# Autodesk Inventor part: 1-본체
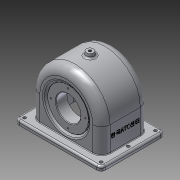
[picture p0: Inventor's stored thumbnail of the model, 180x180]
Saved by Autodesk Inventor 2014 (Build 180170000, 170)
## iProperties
Created: 2015-09
Part Number: 1-본체
Material: 알루미늄 6061
Document SubType Name: Modeling
Designer: Administrator
Density: 2.71 g/cm^3
Appearance: 알루미늄 - 평지
Mass: 735.164 g
Surface Area: 899.785 cm^2
Volume: 271.278 cm^3
Author: Administrator
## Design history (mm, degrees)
sketch "스케치2"
  geometry: L1 (57, 40)-(57, -7); L2 (-57, 40)-(-57, -7); L3 (57, -7)-(-57, -7); C1 r 51 at (0, 40); A1 r 57 centre (0, 40) between (57, 40) and (-57, 40); 2 further points
  constraints: 6 end point, 2 centre point, 2 point on circle, 2 tangent, 1 perpendicular, 1 vertical alignment
  dimensions: "d4" = 51 radius of C1; "d6" = 6 radial gap between concentric circles of C1 A1; "d27" = 40 distance of point (0, 0) C1.centre
extrude "돌출2" join sketch "스케치2" stored distance "d7" = 77; taper "d8" = 0 deg
fillet "모깎기1" dims "d11" = 14
feature "쉘4" dims "d30" = 6, "d31" = 5
sketch "스케치12"
  geometry: L1 (-43, -38.5)-(43, -38.5) reference; L2 (-57, -24.5)-(-57, 24.5) reference; L3 (43, 38.5)-(-43, 38.5) reference; L4 (57, -24.5)-(57, 24.5) reference; L5 (-70, -52)-(70, -52); L6 (70, -52)-(70, 52); L7 (70, 52)-(-70, 52); L8 (-70, 52)-(-70, -52); A1 r 14 centre (-43, -24.5) between (-57, -24.5) and (-43, -38.5) reference; A2 r 14 centre (-43, 24.5) between (-43, 38.5) and (-57, 24.5) reference; A3 r 14 centre (43, 24.5) between (57, 24.5) and (43, 38.5) reference; A4 r 14 centre (43, -24.5) between (43, -38.5) and (57, -24.5) reference; 3 further points
  constraints: 8 end point, 2 midpoint, 2 parallel, 1 horizontal, 1 horizontal alignment, 1 perpendicular, 1 vertical alignment
  dimensions: "d32" = 104 distance of L7.end L5.start; "d33" = 140 distance of L6.end L7.end
extrude "돌출5" join sketch "스케치12" distance "d34" = 7; taper "d35" = 0 deg
sketch "스케치8"
  geometry: L1 (-33.5, 40)-(-17.5, 40); L2 (-17.5, 40)-(-17.5, 68); L3 (-17.5, 68)-(-33.5, 81.426); L4 (-33.5, 81.426)-(-33.5, 40); L5 (-52, -7)-(52, -7) reference; L6 (-33.5, 40)-(-33.5, 83) reference; 1 further point
  constraints: 8 end point, 1 collinear, 1 horizontal, 1 parallel, 1 perpendicular
  dimensions: "d16" = 50 deg angle of L2 L3; "d17" = 16 distance of L1.start L1.end; "d18" = 28 distance of L1.end L2.end; "d36" = 47 distance from line of L1.start L5
revolve "회전1" sketch "스케치8" stored, may be unused: angle "d19" = 90 deg
sketch "스케치9"
  geometry: C1 r 31 at (0, -40); A1 r 43 centre (0, -40) between (-43, -40) and (43, -40) reference; 1 further point
  constraints: 1 centre point, 1 coincident
  dimensions: "d20" = 62 diameter of C1
extrude "돌출3" join sketch "스케치9" distance "d21" = 10; taper "d22" = 0 deg
node "작업 평면1"
sketch "스케치10"
  geometry: C1 r 6 at (70, 52); 1 further point
  constraints: 1 centre point, 1 coincident
  dimensions: "d24" = 12 diameter of C1
extrude "돌출4" join sketch "스케치10" stored distance "d25" = 10; taper "d26" = 10 deg
sketch "스케치16"
  geometry: L1 (-38.5, 40)-(-38.5, 77.195); L2 (-38.5, 77.195)-(-33.5, 73); L3 (-33.5, 73)-(-33.5, 40); L4 (-33.5, 40)-(-38.5, 40); L5 (-24.5, 40)-(24.5, 40) reference; L6 (-33.5, 81.426)-(-33.5, -1.426) reference; L7 (-38.5, 40)-(-38.5, 83) reference; L8 (-24.5, 40)-(-33.5, 40) reference; 1 further point
  constraints: 8 end point, 2 point on line, 1 collinear, 1 parallel, 1 perpendicular, 1 vertical
  dimensions: "d45" = 50 deg angle of L6 L2; "d46" = 33 distance from line of L8 L2.end
revolve "회전2" sketch "스케치16" stored, may be unused: angle "d47" = 90 deg
sketch "스케치17"
  geometry: C1 r 33 at (0, 0) reference; C2 r 33 at (0, 0); 1 further point
  constraints: 1 centre point, 1 coincident
  dimensions: "d48" = 66 diameter of C2
extrude "돌출8" join sketch "스케치17" distance "d49" = 2; taper "d50" = 0 deg
hole "구멍1" diameter "d53" = 40; stored, may be unused: countersink angle "d57" = 90 deg, drill point angle "d59" = 118 deg; dims "d51" = 10, "d52" = 10, "d54" = 6, "d55" = 4, "d56" = 2, "d58" = 8
sketch "스케치18"
  geometry: L1 (0, 0)-(0, 28); C1 r 20 at (0, 0) reference; 1 further point
  constraints: 2 end point, 1 coincident, 1 vertical
  dimensions: "d60" = 28 distance of L1.start L1.end
hole "구멍2" sketch "스케치18" at (0, 28) diameter "d61" = 2.459; stored, may be unused: countersink angle "d65" = 90 deg, drill point angle "d67" = 118 deg; dims "d62" = 7, "d63" = 4, "d64" = 2, "d66" = 9
sketch "스케치19"
  geometry: L1 (0, 0)-(0, -24); C1 r 20 at (0, 0) reference; 1 further point
  constraints: 2 end point, 1 coincident, 1 vertical
  dimensions: "d71" = 24 distance of L1.start L1.end
hole "구멍3" sketch "스케치19" at (0, -24) diameter "d72" = 2.459; stored, may be unused: countersink angle "d76" = 90 deg, drill point angle "d78" = 118 deg; dims "d73" = 6, "d74" = 4, "d75" = 2, "d77" = 8
sketch "스케치20"
  geometry: 1 further point
hole "구멍4" sketch "스케치20" at (0, 0) diameter "d82" = 4.459; stored, may be unused: countersink angle "d86" = 90 deg, drill point angle "d88" = 118 deg; dims "d83" = 7, "d84" = 4, "d85" = 2, "d87" = 9
sketch "스케치21"
  geometry: L1 (15.664, 0.636)-(15.664, 48.364); L2 (15.664, 48.364)-(18.336, 48.364); L3 (18.336, 48.364)-(18.336, 0.636); L4 (18.336, 0.636)-(15.664, 0.636); L5 (47, 76.5)-(47, -27.5) reference; L6 (0, -14)-(40, -14) reference; 4 further points
  constraints: 3 midpoint, 1 horizontal alignment, 2 other
  dimensions: "d89" = 38.5 distance from line of L6 point (18.336, 24.5) (derived); "d90" = 30 distance from line of L5 point (17, 48.364)
feature "엠보싱1" sketch "스케치21" dims "d91" = 0.5, "d92" = 0
fillet "모깎기2" dims "d93" = 3
fillet "모깎기3" dims "d94" = 0.5
fillet "모깎기4" dims "d95" = 1
fillet "모깎기5" dims "d96" = 7
fillet "모깎기6" dims "d97" = 3
chamfer "모따기1" distance "d98" = 1; stored, may be unused: second distance "d99" = 2, angle "d100" = 45 deg
fillet "모깎기7" dims "d101" = 3
sketch "스케치22"
  geometry: L1 (-62, 44)-(62, 44); L2 (62, 44)-(62, -44); L3 (62, -44)-(-62, -44); L4 (-62, -44)-(-62, 44); 4 further points
  constraints: 8 end point, 3 midpoint, 2 parallel, 1 horizontal, 1 horizontal alignment, 1 perpendicular, 1 vertical alignment
  dimensions: "d102" = 124 distance of L2.end L3.end; "d103" = 44 distance of point (62, 0) L1.end; "d104" = 44 distance of L2.end point (62, 0) (derived)
hole "구멍5" sketch "스케치22" at (62, 0), (-62, 44), (-62, 0), (-62, -44), (62, -44), (62, 44) diameter "d105" = 5; stored, may be unused: countersink angle "d109" = 90 deg, drill point angle "d111" = 0 deg; dims "d106" = 6, "d107" = 4, "d108" = 2, "d110" = 8
node "솔리드1"
pattern_circular "원형 패턴1" dims angle "d69" = 360 deg
pattern_circular "원형 패턴2" dims angle "d80" = 360 deg
